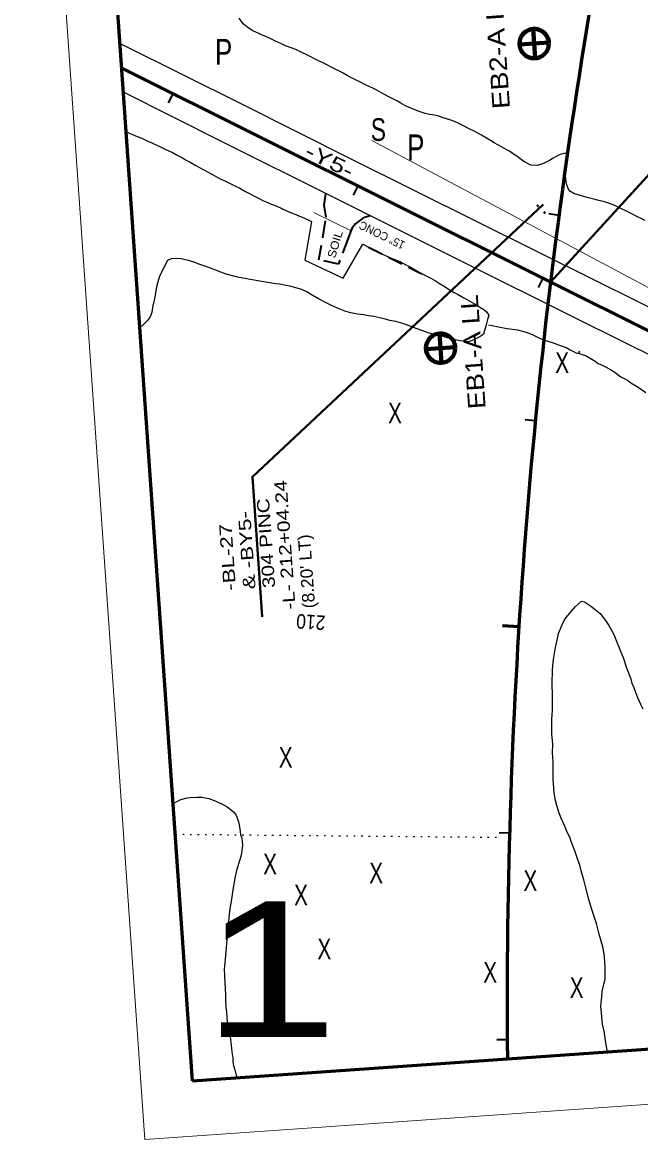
# Model space of a CAD drawing. Extents: x 2399800 to 2400616, y 567351 to 568869.
# Drawn here: x 2399917 to 2400216, y 567968 to 568508 of the extents above; entities that cross this region are included whole.
import ezdxf
from ezdxf.enums import TextEntityAlignment as Align

# ---------------------------------------------------------------- set-up
doc = ezdxf.new("R2010")
doc.units = 0
doc.header["$LTSCALE"] = 2.4
doc.linetypes.add('DOTTED', pattern=[1.5, 0.3, -1.2])
doc.linetypes.add('MEDIUM_DASHED', pattern=[4.5, 3, -1.5])
for name, color, linetype, lineweight in [('1', 7, 'Continuous', 40), ('11', 7, 'Continuous', 25), ('18', 7, 'Continuous', 13), ('21', 7, 'Continuous', 40), ('26', 7, 'MEDIUM_DASHED', 35), ('27', 7, 'Continuous', 80), ('3', 7, 'MEDIUM_DASHED', 35), ('38', 7, 'Continuous', 13), ('4', 7, 'Continuous', 35), ('6', 7, 'Continuous', 13), ('61', 7, 'Continuous', 40), ('62', 7, 'Continuous', 60), ('63', 7, 'Continuous', 35)]:
    doc.layers.add(name, color=color, linetype=linetype, lineweight=lineweight)
for name, color, linetype in [('14', 7, 'Continuous'), ('2', 7, 'Continuous'), ('23', 7, 'Continuous'), ('51', 7, 'Continuous'), ('9', 7, 'Continuous')]:
    doc.layers.add(name, color=color, linetype=linetype)

msp = doc.modelspace()

# ---------------------------------------------------------------- linework, layer by layer
at = {"layer": '1'}
msp.add_line((2399965.144, 568485.991), (2400484.477, 568226.976), dxfattribs=at)
at = {"layer": '11', "linetype": 'DOTTED'}
msp.add_line((2399991.059, 568115.389), (2400148.956, 568113.896), dxfattribs=at)
at = {"layer": '11'}
for points in [[(2400211.666, 568415.633), (2400208.81, 568417.074), (2400207.671, 568417.679), (2400204.74, 568419.13), (2400203.741, 568419.641), (2400201.274, 568420.574), (2400198.863, 568421.346), (2400195.469, 568422.172), (2400193.617, 568422.567), (2400191.037, 568423.209), (2400189.28, 568423.745), (2400186.494, 568424.566), (2400183.943, 568425.434), (2400182.095, 568426.437), (2400181.289, 568427.837), (2400180.356, 568430.015), (2400180.249, 568430.943), (2400179.939, 568433.801), (2400179.846, 568437.162), (2400180.066, 568439.418), (2400180.793, 568442.064), (2400180.947, 568444.404), (2400179.564, 568444.889), (2400177.276, 568444.275), (2400176.225, 568443.804), (2400173.913, 568442.432), (2400172.174, 568441.366), (2400169.319, 568439.913), (2400166.298, 568438.938), (2400163.125, 568439.125), (2400159.839, 568440.775), (2400157.76, 568442.341), (2400156.381, 568443.436), (2400154.832, 568444.4), (2400152.818, 568445.882), (2400151.25, 568446.696), (2400148.898, 568447.919), (2400147.2, 568448.902), (2400145.426, 568449.896), (2400143.588, 568450.975), (2400140.9, 568452.545), (2400139.277, 568453.519), (2400136.086, 568455.308), (2400133.379, 568456.728), (2400130.512, 568458.094), (2400128.225, 568459.231), (2400126.152, 568460.264), (2400123.975, 568461.083), (2400120.751, 568462.038), (2400118.199, 568462.905), (2400115.609, 568463.473), (2400114.112, 568463.669), (2400112.026, 568464.019), (2400109.55, 568464.877), (2400108.606, 568465.228), (2400105.935, 568466.34), (2400103.992, 568467.204), (2400102.544, 568467.774), (2400100.202, 568469.071), (2400098.643, 568469.961), (2400096.076, 568471.287), (2400094.358, 568472.121), (2400090.887, 568474.098), (2400088.684, 568475.301), (2400086.686, 568476.324), (2400085.183, 568477.054), (2400082.456, 568478.325), (2400080.384, 568479.358), (2400078.227, 568480.326), (2400075.744, 568481.717), (2400074.326, 568482.512), (2400072.253, 568483.545), (2400070.844, 568484.415), (2400068.407, 568485.572), (2400066.839, 568486.387), (2400064.422, 568487.693), (2400062.919, 568488.423), (2400061.49, 568489.143), (2400060.052, 568489.789), (2400058.044, 568490.737), (2400056.691, 568491.447), (2400054.404, 568492.584), (2400052.611, 568493.429), (2400049.669, 568494.804), (2400047.577, 568495.687), (2400044.457, 568496.858), (2400042.449, 568497.806), (2400039.648, 568499.086), (2400038.005, 568499.911), (2400034.839, 568501.316), (2400032.822, 568502.189), (2400031.458, 568502.824), (2400028.657, 568504.106), (2400026.334, 568505.552), (2400023.995, 568507.457), (2400021.923, 568510.241)], [(2399967.292, 568455.269), (2399969.251, 568454.423), (2399972.69, 568452.923), (2399974.828, 568452.122), (2399977.821, 568450.753), (2399979.636, 568449.838), (2399982.486, 568448.564), (2399984.529, 568447.62), (2399986.563, 568446.601), (2399989.775, 568445.129), (2399991.647, 568444.052), (2399994.631, 568442.608), (2399996.351, 568441.549), (2399998.224, 568440.472), (2400001.047, 568438.971), (2400002.777, 568437.988), (2400004.507, 568437.006), (2400007.035, 568435.617), (2400008.698, 568434.72), (2400011.017, 568433.511), (2400012.747, 568432.529), (2400015.369, 568431.283), (2400017.26, 568430.358), (2400020.235, 568428.838), (2400022.278, 568427.894), (2400025.101, 568426.392), (2400027.058, 568425.382), (2400029.007, 568424.296), (2400030.746, 568423.39), (2400033.435, 568422.058), (2400035.117, 568421.313), (2400037.454, 568420.256), (2400039.155, 568419.663), (2400042.291, 568418.2), (2400043.089, 568417.794), (2400045.721, 568416.624), (2400047.64, 568415.927), (2400049.331, 568415.258), (2400051.231, 568414.409), (2400053.208, 568413.55)], [(2400218.473, 568412.381), (2400216.241, 568413.358), (2400214.803, 568414.004), (2400211.666, 568415.633)], [(2400053.208, 568413.55), (2400055.982, 568412.285), (2400057.056, 568411.824)], [(2400057.04, 568411.831), (2400053.691, 568393.196), (2400072.371, 568384.475), (2400081.905, 568400.875)], [(2400081.905, 568400.875), (2400083.1, 568400.181), (2400084.336, 568399.567), (2400086.521, 568398.529), (2400088.564, 568397.585), (2400091.387, 568396.084), (2400093.496, 568395.055), (2400095.254, 568394.3), (2400098.123, 568393.178), (2400100.024, 568392.329), (2400102.704, 568390.922), (2400104.376, 568390.101), (2400107.18, 568388.448), (2400109.414, 568387.172), (2400110.859, 568386.379), (2400113.101, 568385.179), (2400114.698, 568384.367), (2400117.008, 568383.083), (2400118.51, 568382.128), (2400121.162, 568380.493), (2400122.882, 568379.435), (2400125.753, 568377.696), (2400127.702, 568376.61), (2400130.649, 568374.862), (2400132.53, 568373.861), (2400135.847, 568371.99), (2400138.509, 568370.432), (2400140.439, 568369.193), (2400141.618, 568368.124), (2400142.8, 568366.438), (2400142.236, 568364.348), (2400141.464, 568361.822), (2400140.75, 568359.134), (2400140.223, 568357.348), (2400138.945, 568356.348), (2400136.803, 568355.223), (2400134.499, 568354.04), (2400132.678, 568353.646), (2400129.935, 568353.905), (2400127.38, 568354.449), (2400125.434, 568354.918), (2400122.813, 568355.547), (2400121.246, 568355.97), (2400118.7, 568356.59), (2400117.133, 568357.012), (2400113.477, 568357.999), (2400110.808, 568358.865), (2400107.644, 568360.1), (2400104.253, 568361.363), (2400101.146, 568362.437), (2400097.87, 568363.377), (2400094.86, 568363.977), (2400092.172, 568364.691), (2400089.997, 568365.188), (2400087.224, 568365.836), (2400084.575, 568366.237), (2400082.23, 568366.601), (2400079.277, 568367.039), (2400075.964, 568367.676), (2400073.58, 568368.353), (2400072.022, 568368.851), (2400069.523, 568369.851), (2400066.749, 568371.115), (2400063.774, 568372.635), (2400060.439, 568374.354), (2400057.273, 568376.206), (2400054.763, 568377.746), (2400052.36, 568378.888), (2400049.387, 568379.792), (2400046.547, 568380.524), (2400044.581, 568380.842), (2400041.572, 568381.441), (2400039.673, 568381.674), (2400035.827, 568382.375), (2400032.723, 568382.832), (2400030.235, 568383.291), (2400028.345, 568383.598), (2400026.389, 568383.992), (2400025.032, 568384.235), (2400023.816, 568384.384), (2400021.186, 568384.937), (2400019.382, 568385.312), (2400015.735, 568386.375), (2400013.066, 568387.241), (2400010.937, 568388.118), (2400009.322, 568388.778), (2400006.823, 568389.777), (2400004.971, 568390.389)], [(2400004.971, 568390.389), (2400002.454, 568391.237), (2400000.981, 568391.802), (2399997.647, 568392.904), (2399995.254, 568393.505), (2399993.981, 568393.815), (2399991.447, 568393.894), (2399989.037, 568393.726), (2399987.331, 568393.01), (2399986.226, 568390.909), (2399985.377, 568389.009), (2399984.583, 568387.564), (2399983.375, 568385.245), (2399982.876, 568383.688), (2399981.984, 568380.174), (2399981.545, 568377.221), (2399981.246, 568375.407), (2399980.617, 568372.786), (2399980.185, 568371.143), (2399979.7, 568367.811), (2399978.975, 568365.664), (2399977.509, 568363.762), (2399974.981, 568361.373), (2399973.894, 568360.859)], [(2400142.718, 568361.851), (2400143.629, 568361.739), (2400148.282, 568360.707), (2400151.739, 568359.976), (2400156.752, 568359.363), (2400159.145, 568358.762), (2400160.93, 568358.235), (2400163.875, 568357.104), (2400165.776, 568356.255), (2400168.836, 568354.802), (2400170.907, 568354.086), (2400174.459, 568352.88), (2400177.423, 568351.901), (2400180.216, 568350.789), (2400182.249, 568349.769), (2400185.158, 568348.334), (2400187.247, 568347.77), (2400190.192, 568346.639), (2400191.922, 568345.657), (2400194.222, 568344.296), (2400195.782, 568343.18), (2400197.682, 568342.331), (2400199.564, 568341.33), (2400202.168, 568339.932), (2400203.746, 568338.968), (2400205.705, 568337.341), (2400207.435, 568336.358), (2400209.887, 568334.98), (2400211.598, 568333.845), (2400214.317, 568332.125), (2400216.029, 568330.99), (2400218.881, 568329.1)], [(2400182.751, 568223.143), (2400184.74, 568225.602), (2400187.749, 568228.106), (2400189.06, 568227.776), (2400192.039, 568225.892), (2400194.352, 568224.089), (2400196.645, 568222.119), (2400199.274, 568218.757), (2400200.84, 568216.37), (2400203.347, 568212.01), (2400204.644, 568208.81), (2400206.591, 568204.012), (2400207.889, 568200.813), (2400209.211, 568196.428), (2400210.131, 568194.289), (2400210.885, 568192.17), (2400211.534, 568190.57), (2400212.102, 568188.305), (2400212.771, 568186.872), (2400213.902, 568183.693), (2400214.823, 568181.554), (2400215.618, 568179.767), (2400216.287, 568178.334), (2400217.354, 568176.008)], [(2400200.182, 568010.071), (2400200.03, 568010.909), (2400199.459, 568014.525), (2400198.613, 568020.034), (2400197.855, 568023.505), (2400197.321, 568028.806), (2400197.062, 568032.216), (2400197.446, 568036.73), (2400197.751, 568039.226), (2400198.532, 568042.846), (2400199.17, 568045.302), (2400199.163, 568048.005), (2400199.176, 568050.875), (2400198.808, 568056.156), (2400198.132, 568060.293), (2400196.263, 568067.109), (2400194.857, 568072.179), (2400192.53, 568079.389), (2400191.208, 568083.773), (2400189.611, 568090.049), (2400188.833, 568093.354), (2400187.511, 568097.738), (2400186.818, 568100.356), (2400185.455, 568104.408), (2400184.47, 568107.4), (2400182.649, 568111.846), (2400182.167, 568113.425), (2400180.431, 568117.184), (2400179.384, 568119.677), (2400177.774, 568123.083), (2400176.894, 568125.555), (2400175.658, 568129.254), (2400175.11, 568131.685), (2400174.393, 568135.489), (2400174.345, 568137.86), (2400174.002, 568141.955), (2400173.89, 568145.178), (2400173.896, 568150.752), (2400173.698, 568154.66), (2400173.728, 568159.049), (2400173.3, 568163.83), (2400173.322, 568170.922), (2400173.706, 568175.435), (2400173.603, 568182.88), (2400173.527, 568187.787), (2400173.591, 568195.211), (2400174.161, 568199.871), (2400175.04, 568205.675), (2400175.821, 568209.296), (2400176.54, 568212.417), (2400178.255, 568216.768), (2400179.6, 568219.475), (2400182.751, 568223.143)], [(2399990.01, 568130.397), (2399992.152, 568131.432), (2399993.772, 568132.247), (2399996.744, 568133.066), (2399998.283, 568133.215), (2400001.505, 568133.328), (2400003.876, 568133.375), (2400007.33, 568132.615), (2400009.911, 568131.624), (2400013.617, 568130.157), (2400016.137, 568128.667), (2400019.221, 568126.262), (2400020.536, 568124.581), (2400021.667, 568121.403), (2400021.983, 568119.844), (2400022.258, 568117.952), (2400022.598, 568115.208), (2400023.227, 568113.442), (2400023.672, 568110.179), (2400023.346, 568107.516), (2400022.895, 568105.206), (2400022.277, 568102.917), (2400020.896, 568098.526), (2400020.115, 568094.905), (2400018.988, 568088.456), (2400018.272, 568083.983)], [(2400018.272, 568083.983), (2400017.536, 568079.343), (2400017.007, 568075.017), (2400016.566, 568068.652), (2400016.077, 568064.658), (2400015.49, 568058.48), (2400015.229, 568054.965), (2400014.785, 568049.952), (2400014.938, 568047.062), (2400014.99, 568043.34), (2400015.204, 568040.949), (2400015.296, 568037.559), (2400015.364, 568035.355), (2400015.602, 568031.779), (2400015.817, 568029.388), (2400016.01, 568026.831), (2400016.245, 568024.606), (2400016.731, 568021.676), (2400017.047, 568020.117), (2400017.574, 568017.519), (2400017.723, 568015.98), (2400018.084, 568013.402), (2400018.363, 568010.159), (2400018.849, 568007.228), (2400018.937, 568005.191), (2400019.233, 568003.465), (2400019.821, 568001.367), (2400020.514, 567998.748), (2400020.945, 567997.537)]]:
    msp.add_lwpolyline(points, dxfattribs=at)
at = {"layer": '18'}
msp.add_line((2400086.216, 568451.054), (2400266.761, 568354.939), dxfattribs=at)
at = {"layer": '21'}
msp.add_lwpolyline([(2400169.181, 568420.085), (2400028.381, 568288.307), (2400033.118, 568220.573)], dxfattribs=at)
at = {"layer": '26'}
for p, q in [((2400084.549, 568399.391), (2400113.482, 568384.96)), ((2400186.819, 568348.384), (2400186.186, 568348.7))]:
    msp.add_line(p, q, dxfattribs=at)
at = {"layer": '27'}
for p, q in [((2400164.274, 568504.988), (2400165.267, 568490.794)), ((2400157.668, 568497.475), (2400157.673, 568497.397)), ((2400171.868, 568498.387), (2400157.673, 568497.397)), ((2400118.977, 568357.627), (2400119.97, 568343.433)), ((2400112.371, 568350.114), (2400112.376, 568350.035)), ((2400126.571, 568351.026), (2400112.376, 568350.035))]:
    msp.add_line(p, q, dxfattribs=at)
for points in [[(2400171.868, 568498.387), (2400164.771, 568497.892), (2400164.274, 568504.988), (2400164.196, 568504.983)], [(2400157.673, 568497.397), (2400164.771, 568497.892), (2400165.267, 568490.794)], [(2400126.571, 568351.026), (2400119.474, 568350.531), (2400118.977, 568357.627), (2400118.899, 568357.622)], [(2400112.376, 568350.035), (2400119.474, 568350.531), (2400119.97, 568343.433)]]:
    msp.add_lwpolyline(points, dxfattribs=at)
for centre in [(2400164.77, 568497.892), (2400119.474, 568350.531)]:
    msp.add_circle(centre, 7.114, dxfattribs=at)
for centre, start, end in [((2400164.77, 568497.892), 4, 94.64426), ((2400164.77, 568497.892), 183.35573, 274), ((2400119.474, 568350.531), 4, 94.64426), ((2400119.474, 568350.531), 183.35573, 274)]:
    msp.add_arc(centre, 7.114, start, end, dxfattribs=at)
at = {"layer": '3', "linetype": 'Continuous', "lineweight": 60}
msp.add_line((2400157.377, 568215.779), (2400149.393, 568216.279), dxfattribs=at)
at = {"layer": '3', "linetype": 'Continuous', "lineweight": 25}
for points in [[(2400483.629, 568239.104), (2400470.246, 568245.798), (2400419.343, 568271.108), (2400362.072, 568299.673), (2400308.009, 568326.642), (2400253.449, 568353.932), (2400194.927, 568382.951), (2400136.831, 568411.76), (2400076.265, 568441.964), (2400023.623, 568468.434), (2399965.535, 568497.344), (2399964.308, 568497.949)], [(2400485.284, 568215.439), (2400462, 568226.988), (2400409.841, 568252.853), (2400354.423, 568280.585), (2400297.876, 568308.829), (2400245.542, 568334.846), (2400186.098, 568364.488), (2400128.133, 568393.345), (2400067.555, 568423.559), (2400013.737, 568450.439), (2399965.96, 568474.329)]]:
    msp.add_lwpolyline(points, dxfattribs=at)
at = {"layer": '3'}
msp.add_lwpolyline([(2400085.469, 568414.624), (2400084.721, 568414.441), (2400083.695, 568414.108), (2400082.697, 568413.699), (2400081.731, 568413.218), (2400080.803, 568412.667), (2400079.919, 568412.049), (2400079.083, 568411.367), (2400078.299, 568410.625), (2400077.572, 568409.827), (2400076.906, 568408.977), (2400076.305, 568408.081), (2400076.277, 568408.036), (2400074.543, 568403.209), (2400069.985, 568391.17), (2400060.545, 568393.314), (2400062.672, 568405.089), (2400064.095, 568413.974), (2400063.174, 568419.797), (2400063.911, 568425.379)], dxfattribs=at)
at = {"layer": '38'}
msp.add_line((2399965.144, 568485.991), (2400484.477, 568226.976), dxfattribs=at)
at = {"layer": '4'}
for p, q in [((2399989.928, 568473.63), (2399987.696, 568469.156)), ((2400079.415, 568428.999), (2400077.183, 568424.525)), ((2400176.752, 568414.798), (2400171.795, 568415.454)), ((2400168.903, 568384.367), (2400166.671, 568379.893)), ((2400165.349, 568315.456), (2400160.372, 568315.94)), ((2400152.846, 568115.887), (2400147.848, 568116.027)), ((2400151.763, 568015.897), (2400146.763, 568015.865))]:
    msp.add_line(p, q, dxfattribs=at)
at = {"layer": '6'}
msp.add_line((2400076.558, 568407.093), (2400058.178, 568416.176), dxfattribs=at)
at = {"layer": '61'}
msp.add_line((2400340.726, 568566.615), (2400172.663, 568382.492), dxfattribs=at)
at = {"layer": '62'}
msp.add_line((2399965.144, 568485.991), (2400484.477, 568226.976), dxfattribs=at)
msp.add_arc((2403051.703, 568034.46), 2900, 170.48821, 180.54867, dxfattribs=at)
at = {"layer": '63', "lineweight": 13}
for p in [(2399917.038, 568815.546), (2400524.992, 568005.982)]:
    msp.add_line(p, (2399976.331, 567967.616), dxfattribs=at)
at = {"layer": '63', "lineweight": 60}
for q in [(2399943.373, 568797.338), (2400498.188, 568030.909)]:
    msp.add_line((2399999.405, 567996.031), q, dxfattribs=at)

# ---------------------------------------------------------------- texts
at = {"layer": '11', "width": 0.75}
for p in [(2400178.317, 568338.571), (2400097.398, 568314.166), (2400044.501, 568147.538), (2400036.94, 568095.932), (2400088.295, 568091.654), (2400162.92, 568087.922), (2400051.928, 568080.952), (2400063.214, 568054.869), (2400143.467, 568043.587), (2400185.34, 568036.153)]:
    msp.add_text('X', height=10, dxfattribs=at).set_placement(p, align=Align.CENTER)
at = {"layer": '14', "width": 0.75}
for p in [(2400014.464, 568487.635), (2400107.481, 568441.428)]:
    msp.add_text('P', height=12.5, dxfattribs=at).set_placement(p, align=Align.CENTER)
at = {"layer": '2'}
msp.add_text(':', height=7.5, rotation=45, dxfattribs=at).set_placement((2400170.158, 568415.758), align=Align.CENTER)
at = {"layer": '21'}
for s, width, p in [('-L- 212+04.24 ', 1.25, (2400049.292, 568224.23)), ('304 PINC', 1.25, (2400039.446, 568234.709)), ('& -BY5-', 1.35, (2400029.969, 568234.046)), ('-BL-27  ', 1.35, (2400020.492, 568233.383)), ("(8.20' LT)", 1.05, (2400058.769, 568224.892))]:
    msp.add_text(s, height=6, rotation=94, dxfattribs=dict(at, width=width)).set_placement(p)
at = {"layer": '23', "width": 1.1}
msp.add_text('SOIL', height=4, rotation=73.424, dxfattribs=at).set_placement((2400070.311, 568400.225), align=Align.CENTER)
at = {"layer": '26', "width": 0.95}
msp.add_text('15" CONC', height=4, rotation=153.938, dxfattribs=at).set_placement((2400091.975, 568406.991), align=Align.CENTER)
at = {"layer": '27'}
for s, width, p in [('EB2-A LL', 1.2, (2400151.055, 568495.473)), ('EB1-A LL', 1.15, (2400139.369, 568349.089))]:
    msp.add_text(s, height=8.438, rotation=94, dxfattribs=dict(at, width=width)).set_placement(p, align=Align.CENTER)
at = {"layer": '51', "width": 1.35}
msp.add_text('1', height=65.62, dxfattribs=at).set_placement((2400037.041, 568017.269), align=Align.CENTER)
at = {"layer": '61'}
for s, rotation, width, p in [('-Y5-', 333.493, 1.4, (2400064.176, 568438.058)), ('210', 176.415, 0.9, (2400056.873, 568221.537))]:
    msp.add_text(s, height=7, rotation=rotation, dxfattribs=dict(at, width=width)).set_placement(p, align=Align.CENTER)
at = {"layer": '9', "width": 0.75}
msp.add_text('S', height=11, dxfattribs=at).set_placement((2400089.359, 568450.815), align=Align.CENTER)

doc.saveas('drawing.dxf')
